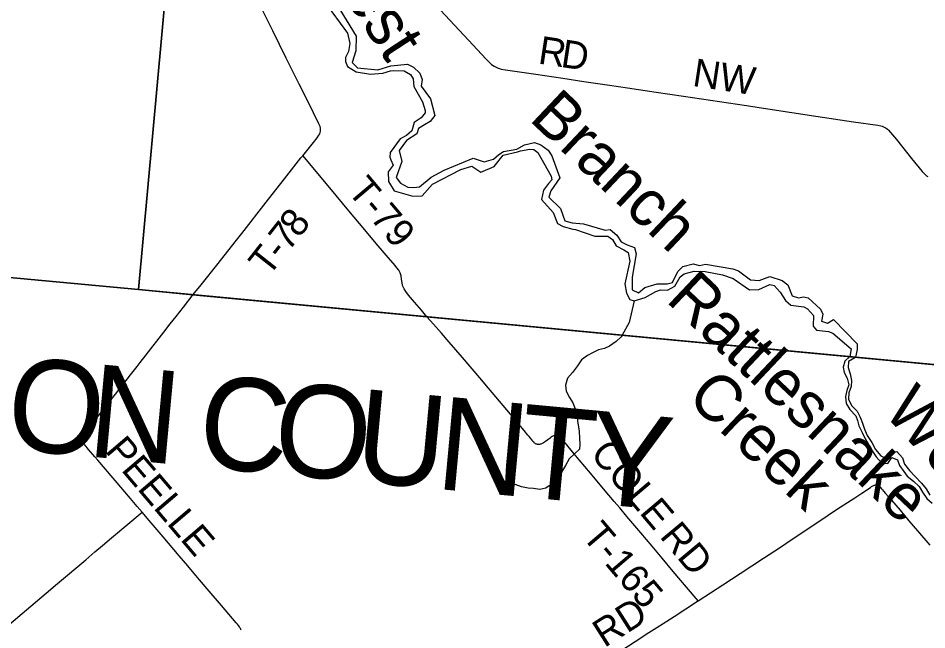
# Model space of a CAD drawing. Extents: x -49 to -8.2, y 9.4 to 23.5.
# Drawn here: x -42.757 to -41.83, y 14.735 to 15.359 of the extents above; entities that cross this region are included whole.
import ezdxf

# ---------------------------------------------------------------- set-up
doc = ezdxf.new("R2010")
doc.units = 0
for name, color, linetype in [('GM_X_Adjacent_County', 7, 'Continuous'), ('GM_X_Adjacent_County_Text', 7, 'Continuous'), ('GM_X_Minor_River', 7, 'Continuous'), ('GM_X_Minor_River_Text', 7, 'Continuous'), ('GM_X_Township', 7, 'Continuous'), ('GM_X_Township_Road', 7, 'Continuous'), ('GM_X_Township_Road_Text', 7, 'Continuous')]:
    doc.layers.add(name, color=color, linetype=linetype)

msp = doc.modelspace()

# ---------------------------------------------------------------- linework, layer by layer
at = {"layer": 'GM_X_Adjacent_County'}
for points in [[(-43.87916, 15.1984), (-43.71722, 15.18325), (-43.34335, 15.14825), (-43.16797, 15.13183), (-42.63454, 15.08208), (-42.60629, 15.39444), (-42.58215, 15.66156), (-42.54815, 16.03753), (-42.51639, 16.39726), (-42.4838, 16.7488), (-42.47792, 16.8137), (-42.43066, 17.336), (-42.42346, 17.41553), (-42.40098, 17.66399), (-42.36067, 18.10983), (-42.33317, 18.41409), (-42.31158, 18.65287), (-42.27744, 19.0304), (-42.26242, 19.19658), (-42.18785, 20.02158)], [(-40.1912, 14.20392), (-40.13536, 14.84654), (-42.63454, 15.08208)]]:
    msp.add_lwpolyline(points, dxfattribs=at)
at = {"layer": 'GM_X_Minor_River'}
msp.add_line((-41.90884, 15.01365), (-41.90319, 15.01311), dxfattribs=at)
msp.add_line((-41.90884, 15.01365), (-41.90319, 15.01311), dxfattribs=at)
for points in [[(-42.44492, 15.37566), (-42.42156, 15.34364), (-42.41922, 15.33316), (-42.42046, 15.325), (-42.42339, 15.31876), (-42.42363, 15.31458), (-42.42141, 15.30961), (-42.41255, 15.304), (-42.39795, 15.30174), (-42.3854, 15.30273), (-42.37739, 15.3053), (-42.37453, 15.30565), (-42.36352, 15.30514), (-42.3573, 15.30127), (-42.35431, 15.29705), (-42.35365, 15.28906), (-42.34491, 15.27356), (-42.34216, 15.26478), (-42.34219, 15.26231), (-42.34625, 15.25723), (-42.35333, 15.25256), (-42.35591, 15.24403), (-42.3611, 15.23915), (-42.36759, 15.2358), (-42.37783, 15.22186), (-42.37808, 15.21711), (-42.37717, 15.21443), (-42.37495, 15.2089), (-42.37978, 15.2023), (-42.37972, 15.19222), (-42.37394, 15.18284), (-42.35463, 15.17749), (-42.34513, 15.17776), (-42.33454, 15.18942), (-42.30566, 15.20467), (-42.29461, 15.20778), (-42.28537, 15.20197), (-42.27162, 15.2077), (-42.26274, 15.219), (-42.24807, 15.22244), (-42.24483, 15.22355), (-42.23531, 15.22534), (-42.23132, 15.22491), (-42.22718, 15.22182), (-42.21361, 15.1979), (-42.21308, 15.19409), (-42.21617, 15.19014), (-42.22138, 15.18336), (-42.22359, 15.17407)], [(-42.43316, 15.37381), (-42.41248, 15.34069), (-42.41304, 15.32567), (-42.4168, 15.31374), (-42.41116, 15.30835), (-42.39048, 15.30621), (-42.37714, 15.31024), (-42.36021, 15.31195), (-42.35416, 15.30902), (-42.34759, 15.30287), (-42.34539, 15.29638), (-42.34623, 15.28954), (-42.3367, 15.2767), (-42.33235, 15.25973), (-42.33717, 15.25351), (-42.34291, 15.25015), (-42.34904, 15.24623), (-42.35081, 15.24093), (-42.36116, 15.23421), (-42.36869, 15.22403), (-42.36598, 15.21278), (-42.37188, 15.19632), (-42.36739, 15.19056), (-42.36003, 15.18648), (-42.35414, 15.18622), (-42.34787, 15.18672), (-42.33596, 15.19685), (-42.32296, 15.20392), (-42.29336, 15.21613), (-42.28201, 15.21219), (-42.27229, 15.21512), (-42.2671, 15.22), (-42.26231, 15.22299), (-42.24861, 15.2253), (-42.24095, 15.22977), (-42.23048, 15.23193), (-42.22424, 15.22977), (-42.21671, 15.22417), (-42.21297, 15.21862), (-42.20489, 15.1959), (-42.21379, 15.1827), (-42.21615, 15.17645), (-42.20413, 15.16472), (-42.19953, 15.15231), (-42.19215, 15.15013), (-42.18057, 15.14924), (-42.15862, 15.14252), (-42.15329, 15.14341), (-42.14671, 15.13763), (-42.14223, 15.13074), (-42.136, 15.12762), (-42.12863, 15.12488), (-42.12681, 15.11839)], [(-42.22359, 15.17407), (-42.2114, 15.16062), (-42.20717, 15.14936), (-42.20151, 15.14625), (-42.19166, 15.14366), (-42.18882, 15.14325), (-42.16895, 15.13656), (-42.15565, 15.1364), (-42.15113, 15.13312), (-42.14741, 15.12681), (-42.13929, 15.12272), (-42.13515, 15.11982), (-42.13336, 15.11106), (-42.13839, 15.08792), (-42.1366, 15.0784), (-42.13326, 15.0719), (-42.12891, 15.07052), (-42.11766, 15.07381), (-42.10695, 15.08015), (-42.10218, 15.0818), (-42.09496, 15.08134), (-42.08732, 15.08543), (-42.08207, 15.09507), (-42.07785, 15.09806), (-42.06756, 15.10079), (-42.05654, 15.10047), (-42.03873, 15.09722), (-42.02795, 15.0933), (-42.01118, 15.08189), (-42.00187, 15.08197), (-41.99059, 15.08735), (-41.98605, 15.08616), (-41.97986, 15.07944), (-41.97465, 15.07082), (-41.969, 15.0662), (-41.95592, 15.06452), (-41.95214, 15.06258), (-41.94596, 15.05566), (-41.94609, 15.04483), (-41.94291, 15.0408), (-41.93058, 15.03914), (-41.92623, 15.03757), (-41.90761, 15.02172), (-41.90884, 15.01365)], [(-42.12681, 15.11839), (-42.13109, 15.09468), (-42.13105, 15.08195), (-42.12444, 15.07864), (-42.11811, 15.08408), (-42.10552, 15.08792), (-42.09526, 15.08781), (-42.08974, 15.08926), (-42.08428, 15.10041), (-42.07928, 15.10549), (-42.0688, 15.10822), (-42.06236, 15.10662), (-42.05626, 15.10807), (-42.02839, 15.10319), (-42.02234, 15.10103), (-42.0101, 15.09195), (-42.00137, 15.09128), (-41.99049, 15.09553), (-41.97782, 15.0912), (-41.97198, 15.08695), (-41.96756, 15.07568), (-41.96112, 15.07352), (-41.95617, 15.07479), (-41.95125, 15.07359), (-41.93866, 15.06204), (-41.93625, 15.05688), (-41.93767, 15.04987), (-41.9318, 15.0479), (-41.92549, 15.05144), (-41.90148, 15.02664), (-41.90142, 15.02095), (-41.90319, 15.01311)], [(-42.12891, 15.07052), (-42.13412, 15.04834), (-42.14111, 15.03559)], [(-42.14111, 15.03559), (-42.14221, 15.03383), (-42.14721, 15.02912), (-42.15392, 15.02443), (-42.15909, 15.02182), (-42.1652, 15.02073), (-42.17151, 15.01756), (-42.17649, 15.01476), (-42.18282, 15.01044), (-42.18688, 15.0042), (-42.1919, 14.9976), (-42.19692, 14.99156), (-42.19908, 14.98473), (-42.19819, 14.97845), (-42.19502, 14.97214), (-42.19165, 14.9664), (-42.18904, 14.96029), (-42.18721, 14.95381), (-42.1867, 14.94772), (-42.1858, 14.9422), (-42.1849, 14.93724), (-42.18459, 14.93058), (-42.18427, 14.92412), (-42.1847, 14.91918), (-42.18989, 14.91447), (-42.19528, 14.90939), (-42.19915, 14.90258), (-42.20322, 14.89577), (-42.2067, 14.89067), (-42.21267, 14.88388), (-42.21919, 14.87957), (-42.22511, 14.8781), (-42.23157, 14.8793), (-42.23691, 14.87935), (-42.24375, 14.88075), (-42.25039, 14.88309), (-42.25666, 14.88467), (-42.26292, 14.88721)], [(-41.90884, 15.01365), (-41.91394, 15.00904), (-41.91571, 15.00279), (-41.91462, 14.99764), (-41.91145, 14.99172), (-41.9098, 14.98504), (-41.91176, 14.97917), (-41.91335, 14.97291), (-41.91266, 14.96586), (-41.90873, 14.95974), (-41.90289, 14.95341), (-41.90103, 14.94864), (-41.89957, 14.94292), (-41.8964, 14.93623), (-41.89303, 14.92993), (-41.88592, 14.91769), (-41.88198, 14.91138), (-41.87652, 14.90543), (-41.87005, 14.9048), (-41.86599, 14.91084), (-41.86011, 14.90851), (-41.85827, 14.90259), (-41.85357, 14.89665), (-41.85019, 14.89187), (-41.84377, 14.88648), (-41.83811, 14.8813), (-41.83474, 14.87556), (-41.83043, 14.86905), (-41.82476, 14.86425)], [(-41.90319, 15.01311), (-41.90362, 15.01237), (-41.91013, 15.00882), (-41.91058, 15.00255), (-41.90855, 14.99606), (-41.90709, 14.9892), (-41.90734, 14.98331), (-41.9097, 14.97667), (-41.91033, 14.97021), (-41.90716, 14.96391), (-41.90151, 14.95796), (-41.89833, 14.95204), (-41.89592, 14.94574), (-41.89389, 14.93963), (-41.89109, 14.93314), (-41.8864, 14.92625), (-41.88267, 14.91899), (-41.87721, 14.91247), (-41.87096, 14.90937), (-41.8669, 14.91523), (-41.86098, 14.91688), (-41.85514, 14.91036), (-41.85312, 14.90388), (-41.84804, 14.89755), (-41.84201, 14.89141), (-41.8356, 14.88469), (-41.8309, 14.87876), (-41.82735, 14.87226)]]:
    msp.add_lwpolyline(points, dxfattribs=at)
at = {"layer": 'GM_X_Township'}
for points in [[(-40.58818, 17.12439), (-40.73433, 17.12609), (-41.0788, 17.13706), (-41.35732, 17.15149), (-41.42352, 17.15606), (-41.91904, 17.28606), (-42.42346, 17.41553), (-42.43066, 17.336), (-42.47792, 16.8137), (-42.4838, 16.7488), (-42.51639, 16.39726), (-42.54815, 16.03753), (-42.58215, 15.66156), (-42.60629, 15.39444), (-42.63454, 15.08208), (-42.5793, 15.07686), (-42.34431, 15.05466), (-41.42871, 14.96816), (-41.35642, 14.96138), (-41.04989, 14.93259), (-40.85025, 14.91381), (-40.65011, 14.89497)], [(-44.11998, 17.3857), (-43.53715, 17.34141), (-43.31353, 17.32442), (-43.02931, 17.30282), (-42.85688, 17.09189), (-42.79924, 17.13787), (-42.75124, 17.07853), (-42.68963, 17.00236), (-42.51339, 16.78539), (-42.4838, 16.7488), (-42.51639, 16.39726), (-42.54815, 16.03753), (-42.58215, 15.66156), (-42.60629, 15.39444), (-42.63454, 15.08208), (-43.16797, 15.13183), (-43.34335, 15.14825), (-43.71722, 15.18325), (-43.87916, 15.1984)], [(-41.67592, 14.20392), (-41.43687, 14.34133), (-41.42313, 14.35354), (-41.3209, 14.4444), (-41.20782, 14.51203), (-40.95249, 14.66474), (-40.84189, 14.72808), (-40.73472, 14.80979), (-40.65011, 14.89497), (-40.85025, 14.91381), (-41.04989, 14.93259), (-41.35642, 14.96138), (-41.42871, 14.96816), (-42.34431, 15.05466), (-42.5793, 15.07686), (-42.63454, 15.08208), (-43.16797, 15.13183), (-43.34335, 15.14825), (-43.71722, 15.18325), (-43.87916, 15.1984), (-44.06357, 15.21525), (-44.15889, 15.08792), (-44.82058, 14.20392)]]:
    msp.add_lwpolyline(points, dxfattribs=at)
at = {"layer": 'GM_X_Township_Road'}
for points in [[(-42.46706, 15.21862), (-42.45617, 15.23201), (-42.45229, 15.23687), (-42.45055, 15.23946), (-42.44983, 15.24084), (-42.44928, 15.24229), (-42.44897, 15.2438), (-42.4489, 15.24533), (-42.44908, 15.24686), (-42.44947, 15.24836), (-42.45063, 15.25125), (-42.46171, 15.27352), (-42.47075, 15.29159), (-42.48387, 15.31804), (-42.4977, 15.34588), (-42.5122, 15.37512), (-42.52681, 15.4043), (-42.53579, 15.4224), (-42.5385, 15.42827), (-42.5387, 15.4287)], [(-42.32657, 15.36716), (-42.29799, 15.33643), (-42.27997, 15.31711), (-42.27669, 15.31379), (-42.27437, 15.31173), (-42.27185, 15.30991), (-42.2705, 15.30913), (-42.26911, 15.30845), (-42.26767, 15.30787), (-42.26619, 15.30739), (-42.26469, 15.30701), (-42.26009, 15.30624), (-42.22931, 15.30189), (-42.20164, 15.29777), (-42.18015, 15.29441), (-42.15402, 15.29047), (-42.13556, 15.28781), (-42.10635, 15.28354), (-42.07869, 15.27931), (-42.01414, 15.26967), (-41.99263, 15.26635), (-41.94347, 15.25891), (-41.90504, 15.25317), (-41.88041, 15.24969), (-41.87736, 15.24906), (-41.87587, 15.24862), (-41.87443, 15.24805), (-41.87304, 15.24737), (-41.87173, 15.24654), (-41.87051, 15.2456), (-41.86936, 15.24456), (-41.86724, 15.24228), (-41.86134, 15.23505), (-41.84579, 15.21564), (-41.83488, 15.20247), (-41.83282, 15.20014), (-41.83048, 15.19809), (-41.82919, 15.19733)], [(-42.57886, 15.07691), (-42.57077, 15.08685), (-42.55343, 15.1088), (-42.53602, 15.1307), (-42.52936, 15.1393), (-42.50438, 15.17106), (-42.48329, 15.19797), (-42.46892, 15.21633), (-42.46706, 15.21862)], [(-42.34034, 15.05442), (-42.3459, 15.06109), (-42.35304, 15.06928), (-42.35907, 15.07639), (-42.36196, 15.08006), (-42.36363, 15.08267), (-42.36433, 15.08404), (-42.36492, 15.08546), (-42.36539, 15.08693), (-42.36572, 15.08844), (-42.36627, 15.09308), (-42.36674, 15.09615), (-42.3677, 15.09908), (-42.36838, 15.10047), (-42.36915, 15.10181), (-42.37095, 15.10434), (-42.37293, 15.10674), (-42.3821, 15.1173), (-42.39011, 15.12681), (-42.40909, 15.14939), (-42.42008, 15.16247), (-42.43298, 15.17799), (-42.46683, 15.21836), (-42.46706, 15.21862)], [(-42.63092, 14.85504), (-42.63609, 14.86093), (-42.64295, 14.86895), (-42.67627, 14.90792), (-42.67931, 14.91146), (-42.68575, 14.91901), (-42.68712, 14.92067), (-42.68808, 14.92189), (-42.68872, 14.92281), (-42.68934, 14.92371), (-42.68975, 14.92441), (-42.69012, 14.92515), (-42.69032, 14.92565), (-42.69053, 14.92622), (-42.69074, 14.92704), (-42.69086, 14.9277), (-42.69094, 14.92844), (-42.69098, 14.92926), (-42.69094, 14.93009), (-42.69086, 14.93099), (-42.69074, 14.93169), (-42.69049, 14.93267), (-42.69008, 14.93362), (-42.68967, 14.93448), (-42.68909, 14.93555), (-42.68839, 14.93674), (-42.68778, 14.93769), (-42.6871, 14.93867), (-42.68617, 14.93991), (-42.68503, 14.94138), (-42.68325, 14.94365), (-42.6793, 14.94871), (-42.67466, 14.95456), (-42.66214, 14.97041), (-42.65175, 14.98358), (-42.64272, 14.99505), (-42.63607, 15.00366), (-42.63301, 15.00757), (-42.62688, 15.0154), (-42.60878, 15.03871), (-42.60236, 15.04709), (-42.59641, 15.05466), (-42.58888, 15.06416), (-42.57886, 15.07691)], [(-42.06371, 14.76452), (-42.07557, 14.77868), (-42.08904, 14.79456), (-42.10042, 14.80812), (-42.11064, 14.82023), (-42.12225, 14.834), (-42.13625, 14.85064), (-42.14369, 14.8594), (-42.14941, 14.86596), (-42.15484, 14.87235), (-42.16515, 14.88478), (-42.17351, 14.8948), (-42.18489, 14.90836), (-42.19003, 14.9146), (-42.19619, 14.92199), (-42.20025, 14.92711), (-42.20159, 14.92882), (-42.20226, 14.92965), (-42.20296, 14.93044), (-42.20341, 14.93093), (-42.20391, 14.93142), (-42.20434, 14.93182), (-42.20506, 14.93238), (-42.2056, 14.9327), (-42.20617, 14.93298), (-42.20679, 14.93319), (-42.20732, 14.93331), (-42.20789, 14.93339), (-42.20851, 14.93344), (-42.20917, 14.93341), (-42.20971, 14.93331), (-42.2104, 14.93315), (-42.2111, 14.9329), (-42.21192, 14.93253), (-42.2126, 14.93217), (-42.21357, 14.93146), (-42.21468, 14.93064), (-42.21939, 14.92714), (-42.22043, 14.92641), (-42.22133, 14.92579), (-42.22199, 14.92542), (-42.22269, 14.92505), (-42.22347, 14.92468), (-42.22413, 14.92443), (-42.22483, 14.92423), (-42.22553, 14.92411), (-42.22614, 14.92407), (-42.2268, 14.92407), (-42.22742, 14.92411), (-42.22804, 14.92423), (-42.22878, 14.92448), (-42.22956, 14.92489), (-42.23013, 14.92526), (-42.23083, 14.92583), (-42.23145, 14.92641), (-42.23223, 14.92727), (-42.23313, 14.92838), (-42.23481, 14.93043), (-42.23615, 14.93216), (-42.23731, 14.93362), (-42.24104, 14.9382), (-42.25505, 14.95484), (-42.27759, 14.98134), (-42.28656, 14.99206), (-42.30424, 15.01291), (-42.31753, 15.02852), (-42.32558, 15.03758), (-42.33383, 15.04686), (-42.34034, 15.05442)], [(-42.06371, 14.76452), (-42.03847, 14.78095), (-42.02085, 14.79261), (-41.99687, 14.80816), (-41.97976, 14.81948), (-41.96785, 14.82736), (-41.93961, 14.84606), (-41.92229, 14.85761), (-41.90387, 14.86974), (-41.89656, 14.87446), (-41.8878, 14.88035), (-41.88657, 14.88113), (-41.8855, 14.88174), (-41.88447, 14.88228), (-41.88386, 14.88253), (-41.88324, 14.88269), (-41.8827, 14.88277), (-41.88221, 14.88277), (-41.88165, 14.88269), (-41.88094, 14.88248), (-41.88032, 14.88224), (-41.87979, 14.88195), (-41.87931, 14.88161), (-41.87872, 14.88117), (-41.87798, 14.88051), (-41.8772, 14.87973), (-41.87642, 14.87891), (-41.87547, 14.87784), (-41.8744, 14.87657), (-41.87238, 14.87422), (-41.8663, 14.86717), (-41.85765, 14.85698), (-41.8486, 14.84633), (-41.83969, 14.83595), (-41.8271, 14.82137)], [(-42.77173, 14.73599), (-42.75353, 14.7515), (-42.72894, 14.77246), (-42.71732, 14.78229), (-42.68856, 14.8065), (-42.67911, 14.81456), (-42.6715, 14.82095), (-42.66221, 14.82873), (-42.63092, 14.85504)], [(-42.52991, 14.73459), (-42.53028, 14.73546), (-42.53069, 14.73623), (-42.53103, 14.73684), (-42.53176, 14.73796), (-42.53278, 14.73944), (-42.53377, 14.74067), (-42.53496, 14.74218), (-42.55016, 14.75987), (-42.56245, 14.77429), (-42.57449, 14.78852), (-42.58451, 14.80039), (-42.59319, 14.81055), (-42.60964, 14.83), (-42.62365, 14.84663), (-42.63092, 14.85504)], [(-42.40314, 14.54735), (-42.40185, 14.54817), (-42.37756, 14.5638), (-42.36185, 14.57385), (-42.33765, 14.58906), (-42.31354, 14.60441), (-42.30096, 14.61243), (-42.29122, 14.61852), (-42.27527, 14.62877), (-42.26553, 14.63486), (-42.25347, 14.64253), (-42.23276, 14.65571), (-42.22224, 14.66232), (-42.20734, 14.67191), (-42.18361, 14.68728), (-42.15981, 14.70253), (-42.12802, 14.72317), (-42.11389, 14.73221), (-42.10319, 14.73913), (-42.08826, 14.74865), (-42.06425, 14.76416), (-42.06371, 14.76452)]]:
    msp.add_lwpolyline(points, dxfattribs=at)

# ---------------------------------------------------------------- texts
at = {"layer": 'GM_X_Adjacent_County_Text'}
for s, rotation, p in [('O', 354.68153, (-42.77163, 14.91984)), ('N', 354.68144, (-42.68824, 14.91207)), ('C', 354.68123, (-42.57623, 14.90164)), ('O', 354.68144, (-42.49948, 14.8945)), ('U', 354.68144, (-42.41608, 14.88673)), ('N', 354.68144, (-42.33269, 14.87897)), ('T', 354.68121, (-42.2493, 14.87121)), ('Y', 354.68144, (-42.17878, 14.86464))]:
    msp.add_text(s, height=0.0947, rotation=rotation, dxfattribs=at).set_placement(p)
at = {"layer": 'GM_X_Minor_River_Text'}
for s, height, rotation, p in [('West', 0.047361, 303.13758, (-42.45924, 15.43297)), ('Branch', 0.047356, 316.61803, (-42.23718, 15.2554)), ('Rattlesnake', 0.0473511, 316.62221, (-42.09756, 15.07058)), ('Creek', 0.047351, 316.62274, (-42.0767, 14.97043)), ('West', 0.04735, 312.55623, (-41.87573, 14.9567))]:
    msp.add_text(s, height=height, rotation=rotation, dxfattribs=at).set_placement(p)
at = {"layer": 'GM_X_Township_Road_Text'}
for s, height, rotation, p in [('R', 0.02841, 351.3298, (-42.22777, 15.31278)), ('D', 0.02841, 351.42266, (-42.20465, 15.30926)), ('NW', 0.028409, 351.34741, (-42.07027, 15.28987)), ('T-79', 0.028409, 310.12676, (-42.42236, 15.1823)), ('8', 0.02841, 51.87672, (-42.47098, 15.13379)), ('7', 0.02841, 51.8653, (-42.4817, 15.12013)), ('T', 0.02841, 51.77385, (-42.502, 15.09434)), ('-', 0.02841, 51.84421, (-42.48885, 15.11103)), ('PEELLE', 0.028409, 310.43645, (-42.66957, 14.91723)), ('COLE', 0.028409, 310.13179, (-42.17466, 14.91406)), ('T-165', 0.028409, 310.31084, (-42.18311, 14.83021)), ('RD', 0.028409, 309.81041, (-42.10364, 14.83006)), ('RD', 0.028409, 32.47033, (-42.15929, 14.71631))]:
    msp.add_text(s, height=height, rotation=rotation, dxfattribs=at).set_placement(p)

doc.saveas('drawing.dxf')
